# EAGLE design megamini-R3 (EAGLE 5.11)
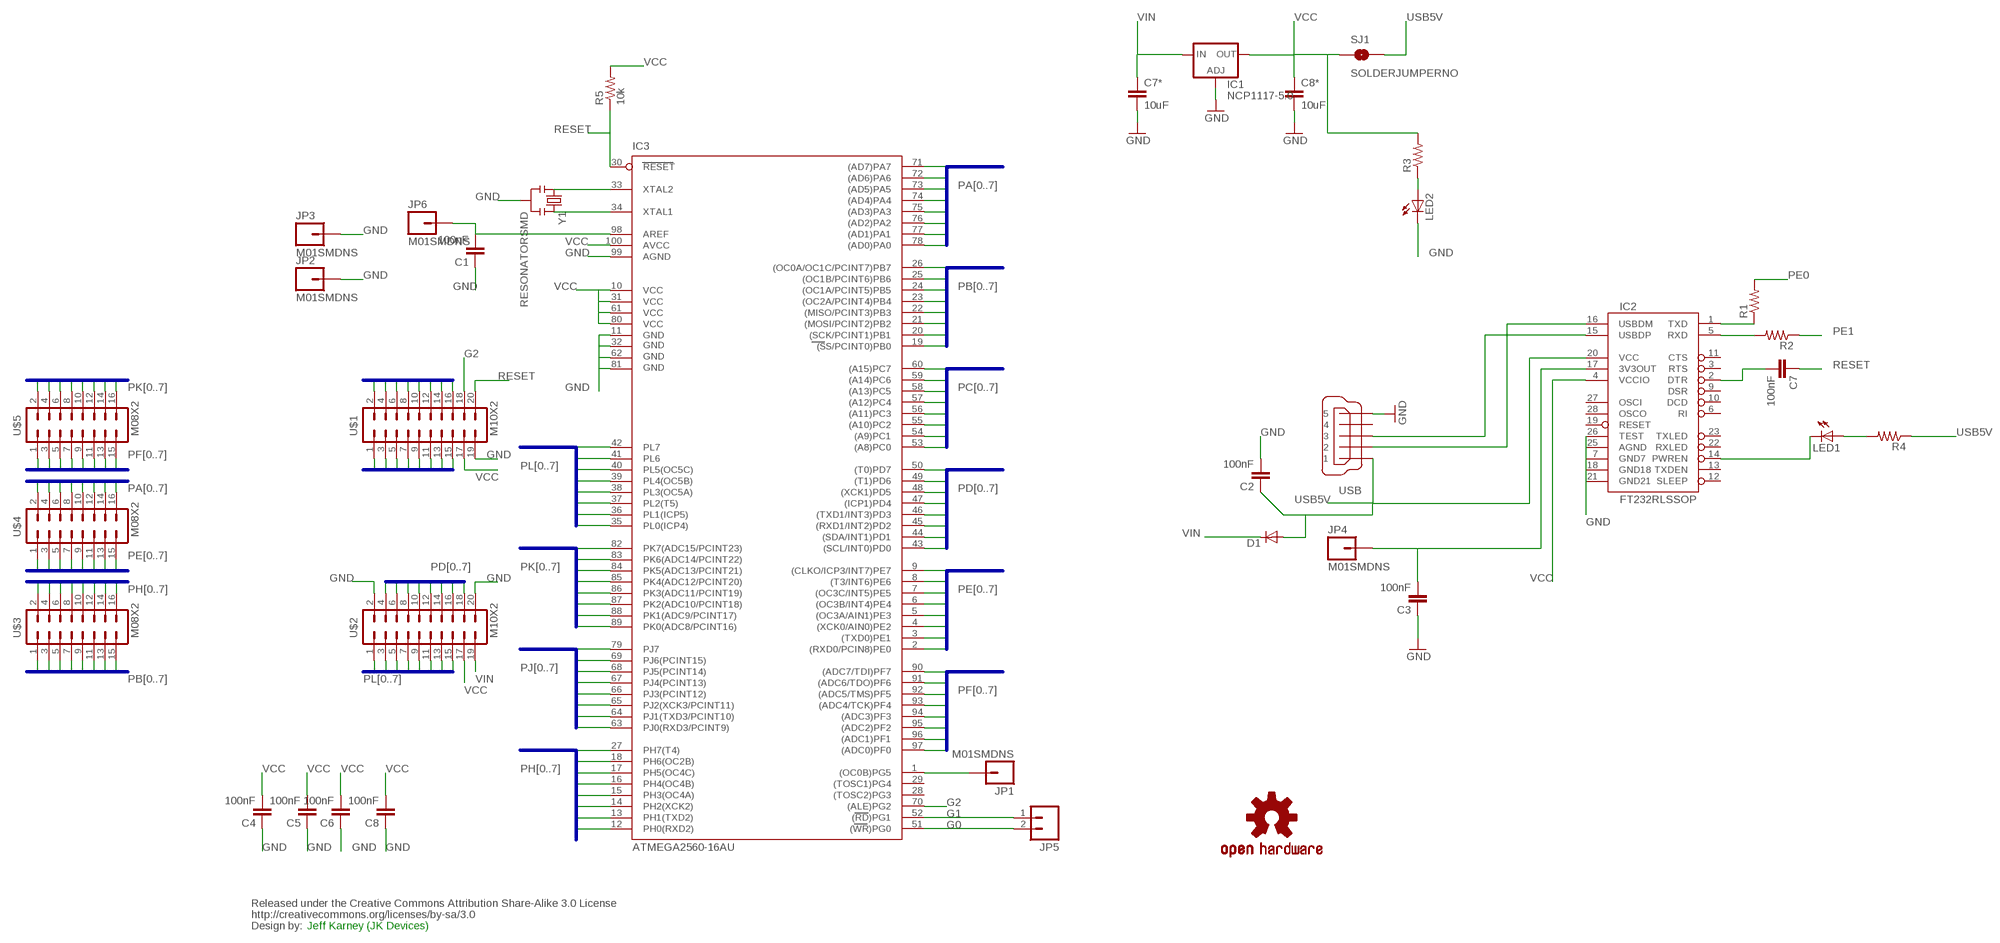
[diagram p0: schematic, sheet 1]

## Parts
C1  100nF  CAP0805  [0805]
C2  100nF  CAP0805  [0805]
C3  100nF  CAP0805  [0805]
C4  100nF  CAP0805  [0805]
C5  100nF  CAP0805  [0805]
C6  100nF  CAP0805  [0805]
C7  100nF  CAP0805  [0805]
C7*  10uF  CAP0805  [0805]
C8  100nF  CAP0805  [0805]
C8*  10uF  CAP0805  [0805]
D1  DIODESOD  [SOD-323]
IC1  NCP1117-5.0  LM317MDT  [DPACK]
IC2  FT232RLSSOP  [SSOP28DB]
IC3  ATMEGA2560-16AU  ATMEGA1280-16AU  [TQFP100]
JP1  M01SMDNS  [1X01NS]
JP2  M01SMDNS  [1X01NS]
JP3  M01SMDNS  [1X01NS]
JP4  M01SMDNS  [1X01NS]
JP5  M02PTH  [1X02]
JP6  M01SMDNS  [1X01NS]
LED1  LED0603  [LED-0603]
LED2  LED0603  [LED-0603]
R1  RESISTOR0805-RES  [0805]
R2  RESISTOR0805-RES  [0805]
R3  RESISTOR0805-RES  [0805]
R4  RESISTOR0805-RES  [0805]
R5  10k  RESISTOR0805-RES  [0805]
SJ1  SOLDERJUMPERNO  [SJ_2S-NO]
U$1  M10X2  [2X10]
U$2  M10X2  [2X10]
U$3  M08X2  [2X8_SMALL]
U$4  M08X2  [2X8_SMALL]
U$5  M08X2  [2X8_SMALL]
U$6  OSHW-LOGOS  [OSHW-LOGO-S]
U$7  CREATIVE_COMMONS  [CREATIVE_COMMONS]
USB  MINI-USB-UX60-MB-5ST  [UX60-MB-5ST]
Y1  RESONATORSMD  [RESONATOR-SMD]

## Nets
G0: IC3.51((WR)PG0) JP5.2
G1: IC3.52((RD)PG1) JP5.1
G2: IC3.70((ALE)PG2) U$1.18
GND: C1.1 C2.2 C3.1 C4.1 C5.1 C6.1 C7*.2 C8*.2 C8.1 IC1.1(ADJ) IC2.7(GND7) IC2.18(GND18) IC2.21(GND21) IC2.25(AGND) IC2.26(TEST) IC3.11(GND) IC3.32(GND1) IC3.62(GND2) IC3.81(GND3) IC3.99(AGND) JP2.1 JP3.1 LED2.C U$1.19 U$2.2 U$2.20 USB.5 Y1.2
N$1: IC2.16(USBDM) USB.2
N$2: IC3.1((OC0B)PG5) JP1.1
N$3: IC2.15(USBDP) USB.3
N$4: C7.2 IC2.2(DTR)
N$5: IC2.1(TXD) R1.1
N$6: IC2.5(RXD) R2.2
N$7: C3.2 IC2.17(3V3OUT) JP4.1
N$8: IC3.33(XTAL2) Y1.1
N$9: IC3.34(XTAL1) Y1.3
N$10: LED2.A R3.1
N$11: LED1.A R4.2
N$12: IC2.14(PWREN) LED1.C
N$13: C1.2 IC3.98(AREF) JP6.1
PA0: IC3.78((AD0)PA0) U$4.2
PA1: IC3.77((AD1)PA1) U$4.4
PA2: IC3.76((AD2)PA2) U$4.6
PA3: IC3.75((AD3)PA3) U$4.8
PA4: IC3.74((AD4)PA4) U$4.10
PA5: IC3.73((AD5)PA5) U$4.12
PA6: IC3.72((AD6)PA6) U$4.14
PA7: IC3.71((AD7)PA7) U$4.16
PB0: IC3.19((SS/PCINT0)PB0) U$3.15
PB1: IC3.20((SCK/PCINT1)PB1) U$3.13
PB2: IC3.21((MOSI/PCINT2)PB2) U$3.11
PB3: IC3.22((MISO/PCINT3)PB3) U$3.9
PB4: IC3.23((OC2A/PCINT4)PB4) U$3.7
PB5: IC3.24((OC1A/PCINT5)PB5) U$3.5
PB6: IC3.25((OC1B/PCINT6)PB6) U$3.3
PB7: IC3.26((OC0A/OC1C/PCINT7)PB7) U$3.1
PC0: IC3.53((A8)PC0) U$1.15
PC1: IC3.54((A9)PC1) U$1.13
PC2: IC3.55((A10)PC2) U$1.11
PC3: IC3.56((A11)PC3) U$1.9
PC4: IC3.57((A12)PC4) U$1.7
PC5: IC3.58((A13)PC5) U$1.5
PC6: IC3.59((A14)PC6) U$1.3
PC7: IC3.60((A15)PC7) U$1.1
PD0: IC3.43((SCL/INT0)PD0) U$2.4
PD1: IC3.44((SDA/INT1)PD1) U$2.6
PD2: IC3.45((RXD1/INT2)PD2) U$2.8
PD3: IC3.46((TXD1/INT3)PD3) U$2.10
PD4: IC3.47((ICP1)PD4) U$2.12
PD5: IC3.48((XCK1)PD5) U$2.14
PD6: IC3.49((T1)PD6) U$2.16
PD7: IC3.50((T0)PD7) U$2.18
PE0: IC3.2((RXD0/PCIN8)PE0) R1.2 U$4.15
PE1: IC3.3((TXD0)PE1) R2.1 U$4.13
PE2: IC3.4((XCK0/AIN0)PE2) U$4.11
PE3: IC3.5((OC3A/AIN1)PE3) U$4.9
PE4: IC3.6((OC3B/INT4)PE4) U$4.7
PE5: IC3.7((OC3C/INT5)PE5) U$4.5
PE6: IC3.8((T3/INT6)PE6) U$4.3
PE7: IC3.9((CLKO/ICP3/INT7)PE7) U$4.1
PF0: IC3.97((ADC0)PF0) U$5.15
PF1: IC3.96((ADC1)PF1) U$5.13
PF2: IC3.95((ADC2)PF2) U$5.11
PF3: IC3.94((ADC3)PF3) U$5.9
PF4: IC3.93((ADC4/TCK)PF4) U$5.7
PF5: IC3.92((ADC5/TMS)PF5) U$5.5
PF6: IC3.91((ADC6/TDO)PF6) U$5.3
PF7: IC3.90((ADC7/TDI)PF7) U$5.1
PH0: IC3.12(PH0(RXD2)) U$3.16
PH1: IC3.13(PH1(TXD2)) U$3.14
PH2: IC3.14(PH2(XCK2)) U$3.12
PH3: IC3.15(PH3(OC4A)) U$3.10
PH4: IC3.16(PH4(OC4B)) U$3.8
PH5: IC3.17(PH5(OC4C)) U$3.6
PH6: IC3.18(PH6(OC2B)) U$3.4
PH7: IC3.27(PH7(T4)) U$3.2
PJ0: IC3.63(PJ0(RXD3/PCINT9)) U$1.2
PJ1: IC3.64(PJ1(TXD3/PCINT10)) U$1.4
PJ2: IC3.65(PJ2(XCK3/PCINT11)) U$1.6
PJ3: IC3.66(PJ3(PCINT12)) U$1.8
PJ4: IC3.67(PJ4(PCINT13)) U$1.10
PJ5: IC3.68(PJ5(PCINT14)) U$1.12
PJ6: IC3.69(PJ6(PCINT15)) U$1.14
PJ7: IC3.79(PJ7) U$1.16
PK0: IC3.89(PK0(ADC8/PCINT16)) U$5.16
PK1: IC3.88(PK1(ADC9/PCINT17)) U$5.14
PK2: IC3.87(PK2(ADC10/PCINT18)) U$5.12
PK3: IC3.86(PK3(ADC11/PCINT19)) U$5.10
PK4: IC3.85(PK4(ADC12/PCINT20)) U$5.8
PK5: IC3.84(PK5(ADC13/PCINT21)) U$5.6
PK6: IC3.83(PK6(ADC14/PCINT22)) U$5.4
PK7: IC3.82(PK7(ADC15/PCINT23)) U$5.2
PL0: IC3.35(PL0(ICP4)) U$2.1
PL1: IC3.36(PL1(ICP5)) U$2.3
PL2: IC3.37(PL2(T5)) U$2.5
PL3: IC3.38(PL3(OC5A)) U$2.7
PL4: IC3.39(PL4(OC5B)) U$2.9
PL5: IC3.40(PL5(OC5C)) U$2.11
PL6: IC3.41(PL6) U$2.13
PL7: IC3.42(PL7) U$2.15
RESET: C7.1 IC3.30(RESET) R5.1 U$1.20
USB5V: C2.1 D1.2(A) IC2.20(VCC) R4.1 SJ1.2 USB.1
VCC: C4.2 C5.2 C6.2 C8*.1 C8.2 IC1.4(OUT) IC2.4(VCCIO) IC3.10(VCC) IC3.31(VCC1) IC3.61(VCC2) IC3.80(VCC3) IC3.100(AVCC) R3.2 R5.2 SJ1.1 U$1.17 U$2.17
VIN: C7*.1 D1.1(C) IC1.3(IN) U$2.19
Unconnected: IC2.3(RTS) IC2.6(RI) IC2.9(DSR) IC2.10(DCD) IC2.11(CTS) IC2.12(SLEEP) IC2.13(TXDEN) IC2.19(RESET) IC2.22(RXLED) IC2.23(TXLED) IC2.27(OSCI) IC2.28(OSCO) IC3.28((TOSC2)PG3) IC3.29((TOSC1)PG4) USB.4

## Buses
PB[0..7]
PH[0..7]
PE[0..7]
PA[0..7]
PF[0..7]
PK[0..7]
PL[0..7]
PD[0..7]
PC[0..7]
PJ[0..7]

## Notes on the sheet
- Jeff Karney (JK Devices)

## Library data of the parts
C1-C7 C7* C8 C8* = SparkFun:CAP: Capacitor
D1 = SparkFun:DIODE: Diode
IC1 = v-reg:LM317?*: 500 mA Adjustable Output Positive Voltage Regulator Source: http://www.onsemi.co.jp .. LM317M-D.PDF
IC2 = SparkFun:FT232RL: USB UART FT232RL 4th Generation USB UART (USB <-> Serial) Controller. Spark Fun Electronics SKU : COM-00650
IC3 = atmel-2005:ATMEGA*: MICROCONTROLLER 64/128/256 Kbytes FLASH 4 Kbytes EEPROM 8 Kbytes SRAM 86 General Purpose I/O pins 12-channels16-bit PWM 4 x Serial USARTs 16-channels 10-bit A/D
JP1-JP4 JP6 = SparkFun:M01: Header 1
JP5 = SparkFun:M02: Header 2
LED1 LED2 = SparkFun:LED: LEDs
R1-R5 = SparkFun:RESISTOR: Resistor
SJ1 = SparkFun:SOLDERJUMPER: Solder Jumper
U$1 U$2 = SparkFun:M10X2: This was SPECIALLY designed to be used with our Graphic LCD Backpack. Be sure you want to use this! It is not only staggered on each line of header holes, but IT IS ALSO offset of the center point of the top and bottom lines by 5 mil. This causes the headers to lock into place on the "standard"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
U$3-U$5 = SparkFun:M08X2
U$6 = SparkFun:OSHW-LOGO: Open Source Hardware Logo This logo indicates the piece of hardware it is found on incorporates a OSHW license and/or adheres to the definition of open source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
U$7 = SparkFun:CREATIVE_COMMONS
USB = con-hirose:MINI-USB-: MINI USB Connector Source: http://www.hirose.co.jp/cataloge_hp/e24000019.pdf; OC_FARNELL: unknown; OC_NEWARK: unknown
Y1 = SparkFun:RESONATOR: Resonator Small SMD resonator. This is the itty bitty 10/20MHz resonators with built in caps. CSTCE10M0G55 and CSTCE20M0V53. Footprint has been reviewed closely but hasn't been tested yet.

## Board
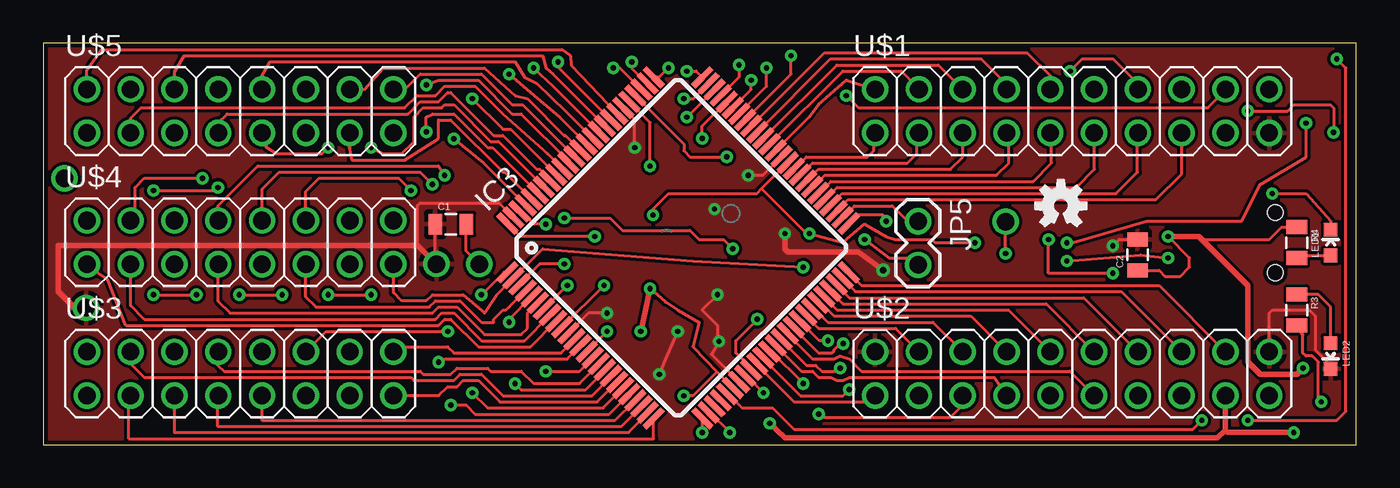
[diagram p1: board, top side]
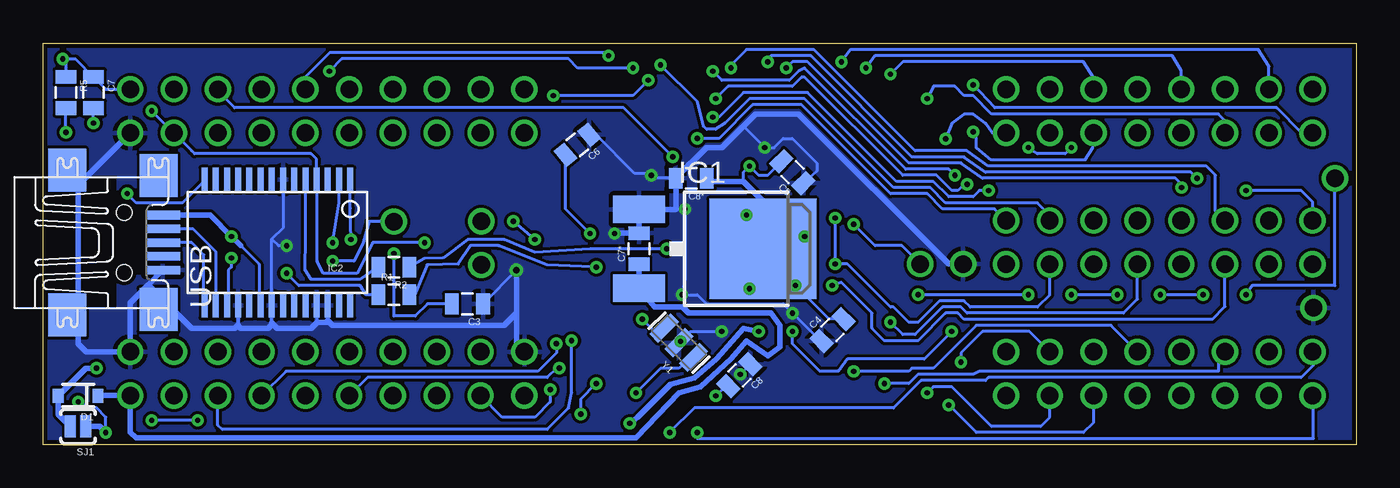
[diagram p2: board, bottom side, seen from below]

Size 76.17 x 23.32 mm. Coordinates in mm from the lower left corner, seen from the top.
Outline: 0,0 76.17,0 76.17,23.32 0,23.32 0,0
Copper layers (1*16): Top 0.0356mm / dielectric 1.5011mm / Bottom 0.0356mm
Design rules "SilverCircuits *": minimum track width 7mil, minimum drill 12mil, track to track 7mil, track to pad 7mil, pad to pad 7mil, via to via 7mil, smd to smd 0mil, copper to edge 10mil, drill to drill 8mil, minimum pad ring 10mil, minimum via ring 8mil, stop-mask expansion 4mil, vias tented up to drill 14mil, thermal gap 10mil

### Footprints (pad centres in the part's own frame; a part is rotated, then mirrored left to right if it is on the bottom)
0805 = smd 0.8 x 1.2: 1 -0.9,0; 2 0.9,0
SOD-323 = smd 0.63 x 0.83: 1 -1.15,0; 2 1.15,0
DPACK = smd 1.6 x 3: 1 -2.28,-4.8; 3 2.28,-4.8 | smd 5.8 x 6.2: 4 0,2.38
SSOP28DB = smd 0.348 x 1.397: 1 -4.225,-3.656; 2 -3.575,-3.656; 3 -2.925,-3.656; 4 -2.275,-3.656; 5 -1.625,-3.656; 6 -0.975,-3.656; 7 -0.325,-3.656; 8 0.325,-3.656; 9 0.975,-3.656; 10 1.625,-3.656; 11 2.275,-3.656; 12 2.925,-3.656; 13 3.575,-3.656; 14 4.225,-3.656; 15 4.225,3.656; 16 3.575,3.656; 17 2.925,3.656; 18 2.275,3.656; 19 1.625,3.656; 20 0.975,3.656; 21 0.325,3.656; 22 -0.325,3.656; 23 -0.975,3.656; 24 -1.625,3.656; 25 -2.275,3.656; 26 -2.925,3.656; 27 -3.575,3.656; 28 -4.225,3.656
TQFP100 = smd 1.5 x 0.35: 1 -8,6; 2 -8,5.5; 3 -8,5; 4 -8,4.5; 5 -8,4; 6 -8,3.5; 7 -8,3; 8 -8,2.5; 9 -8,2; 10 -8,1.5; 11 -8,1; 12 -8,0.5; 13 -8,0; 14 -8,-0.5; 15 -8,-1; 16 -8,-1.5; 17 -8,-2; 18 -8,-2.5; 19 -8,-3; 20 -8,-3.5; 21 -8,-4; 22 -8,-4.5; 23 -8,-5; 24 -8,-5.5; 25 -8,-6; 51 8,-6; 52 8,-5.5; 53 8,-5; 54 8,-4.5; 55 8,-4; 56 8,-3.5; 57 8,-3; 58 8,-2.5; 59 8,-2; 60 8,-1.5; 61 8,-1; 62 8,-0.5; 63 8,0; 64 8,0.5; 65 8,1; 66 8,1.5; 67 8,2; 68 8,2.5; 69 8,3; 70 8,3.5; 71 8,4; 72 8,4.5; 73 8,5; 74 8,5.5; 75 8,6 | smd 0.35 x 1.5: 26 -6,-8; 27 -5.5,-8; 28 -5,-8; 29 -4.5,-8; 30 -4,-8; 31 -3.5,-8; 32 -3,-8; 33 -2.5,-8; 34 -2,-8; 35 -1.5,-8; 36 -1,-8; 37 -0.5,-8; 38 0,-8; 39 0.5,-8; 40 1,-8; 41 1.5,-8; 42 2,-8; 43 2.5,-8; 44 3,-8; 45 3.5,-8; 46 4,-8; 47 4.5,-8; 48 5,-8; 49 5.5,-8; 50 6,-8; 76 6,8; 77 5.5,8; 78 5,8; 79 4.5,8; 80 4,8; 81 3.5,8; 82 3,8; 83 2.5,8; 84 2,8; 85 1.5,8; 86 1,8; 87 0.5,8; 88 0,8; 89 -0.5,8; 90 -1,8; 91 -1.5,8; 92 -2,8; 93 -2.5,8; 94 -3,8; 95 -3.5,8; 96 -4,8; 97 -4.5,8; 98 -5,8; 99 -5.5,8; 100 -6,8
1X01NS = drill 1.016 pad 1.524 round: 1 0,0
1X02 = drill 1.016 pad 1.524 round: 1 0,0; 2 2.54,0
LED-0603 = smd 0.8 x 0.8: A 0,-0.75; C 0,0.75
SJ_2S-NO = smd 0.635 x 1.27: 1 -0.45,0; 2 0.45,0
2X10 = drill 1.016 pad 1.524 round: 1 -11.43,-1.27; 2 -11.43,1.27; 3 -8.89,-1.27; 4 -8.89,1.27; 5 -6.35,-1.27; 6 -6.35,1.27; 7 -3.81,-1.27; 8 -3.81,1.27; 9 -1.27,-1.27; 10 -1.27,1.27; 11 1.27,-1.27; 12 1.27,1.27; 13 3.81,-1.27; 14 3.81,1.27; 15 6.35,-1.27; 16 6.35,1.27; 17 8.89,-1.27; 18 8.89,1.27; 19 11.43,-1.27; 20 11.43,1.27
2X8_SMALL = drill 1.016 pad 1.524 round: 1 0,0; 2 0,2.54; 3 2.54,0; 4 2.54,2.54; 5 5.08,0; 6 5.08,2.54; 7 7.62,0; 8 7.62,2.54; 9 10.16,0; 10 10.16,2.54; 11 12.7,0; 12 12.7,2.54; 13 15.24,0; 14 15.24,2.54; 15 17.78,0; 16 17.78,2.54
UX60-MB-5ST = smd 2 x 0.5: 1 2.25,1.6; 2 2.25,0.8; 3 2.25,0; 4 2.25,-0.8; 5 2.25,-1.6 | smd 2.2 x 2.5: M1 -3.3,-4.2; M2 -3.3,4.2; M3 2,3.882; M4 2,-3.882 | hole 0.9: 0,-1.75; 0,1.75
RESONATOR-SMD = smd 0.7 x 1.7: 1 -1.2,0; 2 0,0; 3 1.2,0

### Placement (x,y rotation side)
C1  23.65,12.8 0 top
C2  63.47,11.02 90 top
C3  51.56,8.18 180 bottom
C4  30.38,6.66 45 bottom
C5  32.72,15.82 135 bottom
C6  45.19,17.41 220 bottom
C7  73.25,20.45 270 bottom
C7*  41.61,11.38 90 bottom
C8  35.79,4.04 225 bottom
C8*  38.58,15.47 180 bottom
D1  74.14,2.84 180 bottom
IC1  36.8,11.38 270 bottom
IC2  62.59,11.73 180 bottom
IC3  36.83,11.43 45 top
JP1  1.24,15.47 0 top
JP2  2.49,7.95 0 top
JP3  22.81,10.49 0 top
JP4  55.83,12.95 0 top
JP5  50.75,12.98 270 top
JP6  25.3,10.49 0 top
LED1  74.68,11.73 0 top
LED2  74.68,5.16 180 top
R1  55.83,8.71 0 bottom
R2  55.83,10.31 180 bottom
R3  72.72,7.82 270 top
R4  72.72,11.73 270 top
R5  74.85,20.45 270 bottom
SJ1  74.14,1.07 180 bottom
U$1  59.69,19.37 0 top
U$2  59.69,4.13 0 top
U$3  2.54,2.86 0 top
U$4  2.54,10.48 0 top
U$5  2.54,18.1 0 top
U$6  59.03,13.87 0 top
U$7  not placed on the board
USB  71.48,11.73 0 bottom
Y1  39.29,5.93 135 bottom

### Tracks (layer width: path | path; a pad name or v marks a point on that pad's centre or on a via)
G0  (via drill 0.3)
  Top 0.178: IC3.51 47.22,13.34 48.72,13.34 48.9,13.16 v48.9,12.98 | v47.65,11.91 49.07,10.85 50.32,10.85 50.72,10.44 JP5.2
  Bottom 0.178: v47.65,11.91 v48.9,12.98
G1
  Top 0.178: IC3.52 47.05,13.87 49.25,13.87 50.14,12.98 JP5.1
G2  (via drill 0.3)
  Top 0.178: IC3.70 41.07,20.62 v41.07,21.16 | v46.58,20.27 47.3,19.56 67.56,19.56 68.58,20.57 U$1.18
  Bottom 0.178: v41.07,21.16 41.96,20.27 v46.58,20.27
GND  (via drill 0.3, 0.38)
  Top 0.178: IC3.99 26.44,14.05 21.87,14.05 21.72,13.89 21.72,11.58 | IC3.32 38.76,5.26 v39.2,6.01 | 39.12,6.04 39.12,6.93 38.23,7.82 v39.12,8.71 | 39.12,6.04 v39.2,6.01 | IC3.62 41.75,15.65 v40.89,15.65 | IC3.81 34.31,18.89 v34.31,17.25 | v39.2,6.01 39.12,5.93 39.12,6.04 | IC3.11 31.63,7.64 v32.72,7.64 | LED2.C 74.68,4.62 73.79,5.51 73.79,7.47 73.43,7.82 71.3,7.82 71.12,7.64 U$2.20 | C1.1 22.75,10.55 JP3.1 | C2.2 62.42,11.92 v62.05,11.56 | v35.74,4.09 36.09,4.98 v36.8,6.58
  Top 0.305: 1.83,7.95 0.89,8.89 0.89,11.58 21.72,11.58 JP3.1 | v48.72,10.13 47.3,11.2 43.2,11.2 43.03,11.38 v43.03,12.27
  Top 0.356: JP2.1 1.83,7.95
  Bottom 0.178: 39.47,13.69 v38.94,13.69 38.94,9.6 v39.12,8.71 38.23,8.71 37.69,8.18 33.25,8.18 v32.72,7.64 31.09,6.03 C4.1 | C8*.2 40.72,15.47 v40.89,15.65 41,15.75 41.86,15.75 44.1,17.99 C6.1 | 35.65,18.4 35.47,18.4 v34.31,17.25 33.78,17.25 33.25,17.78 32.72,17.78 31.29,16.36 31.29,15.9 C5.1 | Y1.2 39.2,5.83 v39.2,6.01 38.63,6.58 v36.8,6.58 | 64.86,6.9 IC2.18 64.86,6.97 | 62.94,6.93 62.94,8.05 IC2.21 | 62.91,7.08 IC2.21 | 60.27,7.11 60.27,8.04 IC2.25 | 59.74,7.11 59.66,7.19 IC2.26 59.66,7.21 | IC2.7 62.23,15.36 62.23,12.62 62.91,11.94 | IC2.21 62.91,11.94 | v48.72,10.13 C3.1 | v62.05,11.56 62.52,11.56 62.91,11.94 | C8.1 | v35.74,4.09 C8.1
  Bottom 0.305: JP3.1 23.65,10.49 32.36,19.2 34.85,19.2 35.65,18.4 36.8,17.25 37.7,17.25 C8*.2 39.47,15.46 39.47,13.69 39.5,13.66 IC1.1 C7*.2 43.02,12.28 v43.03,12.27 | 70.08,9.28 71.12,8.24 U$2.20 73.67,5.4 74.14,5.87 74.14,15.07 U$1.19 | 70.08,9.28 USB.5 | 64.86,6.9 64.72,6.76 63.12,6.76 62.94,6.93 | 62.91,7.08 62.59,6.76 60.63,6.76 60.27,7.11 59.74,7.11 | 64.86,6.97 65.08,6.76 67.56,6.76 70.08,9.28 | U$2.2 48.72,5.86 48.72,7.64 | v48.72,10.13 48.72,7.64 | 59.66,7.21 59.38,6.93 49.43,6.93 48.72,7.64
  pour Top: -2.31,25.43 -2.31,-2.67 79.3,-2.67 78.94,26.49 -0.36,25.96
  pour Bottom: -0.53,24.18 80.72,24.18 80.72,-1.07 -3.2,-1.07 -3.2,24
N$1
  Bottom 0.178: USB.2 67.47,12.54 66.14,11.2 66.14,8.1 IC2.16
N$2  (via drill 0.3)
  Top 0.178: IC3.1 26.73,10.02 v25.43,8.71 | v16.54,8.71 v19.02,8.71 | v11.38,8.71 v13.87,8.71 | v6.4,8.71 v8.89,8.71
  Bottom 0.178: v19.02,8.71 v25.43,8.71 | v13.87,8.71 v16.54,8.71 | v8.89,8.71 v11.38,8.71 | JP1.1 1.25,9.25 6.04,9.25 v6.4,8.71
N$3
  Bottom 0.178: USB.3 67.56,11.73 66.85,11.02 66.85,8.12 IC2.15
N$4  (via drill 0.3)
  Top 0.178: v59.38,11.73 59.74,11.73 64.01,12.98 69.52,12.98 70.59,15.11 73.25,16.71 v73.25,18.67
  Bottom 0.178: IC2.2 59.01,14.06 v59.38,11.73 | v73.25,18.67 C7.2
N$5  (via drill 0.3)
  Top 0.178: v62.05,9.96 58.32,9.96 v58.32,11.91
  Bottom 0.178: R1.1 57.44,8.71 57.78,9.25 61.34,9.25 v62.05,9.96 | v58.32,11.91 58.36,13.73 IC2.1
N$6
  Bottom 0.178: R2.2 57.78,9.6 60.63,9.6 60.98,10.13 60.96,12.07 IC2.5
N$7  (via drill 0.3)
  Top 0.178: v65.25,10.85 63.65,11.02 v59.38,10.67 | v55.83,11.1 JP4.1
  Bottom 0.178: IC2.17 65.43,8.16 65.43,10.13 65.25,10.31 v65.25,10.85 | v59.38,10.67 58.14,10.67 57.61,11.73 57.28,12.95 JP4.1 | v55.83,11.1 55.83,7.47 54.59,7.47 53.87,8.18 C3.2
N$8  (via drill 0.3)
  Top 0.178: IC3.33 40.8,4 v41.78,3.02
  Bottom 0.178: v41.78,3.02 40.36,4.45 39.29,4.45 38.66,5.08 Y1.1
N$9  (via drill 0.3)
  Top 0.178: IC3.34 41.07,4.44 40.18,5.33 40.18,6.04 v41.43,7.29
  Bottom 0.178: v41.43,7.29 40.52,6.4 Y1.3
N$10
  Top 0.178: R3.1 73.95,8.72 74.68,8 LED2.A
N$11
  Top 0.178: LED1.A 72.87,10.98 R4.2
N$12  (via drill 0.3)
  Top 0.178: LED1.C 74.68,12.98 73.25,14.58 v71.3,14.58
  Bottom 0.178: IC2.14 66.81,15.33 68.1,14.05 70.76,14.05 v71.3,14.58
N$13  (via drill 0.3)
  Top 0.178: C1.2 24.55,11.24 JP6.1 | IC3.98 27.7,13.55 28.45,12.8 v29.16,12.8
  Bottom 0.178: v29.16,12.8 27.91,11.56 26.36,11.56 JP6.1
PA0  (via drill 0.3)
  Top 0.178: v6.4,14.76 9.96,14.76 v10.13,14.94 | v33.07,21.87 33.46,21.87 IC3.78
  Bottom 0.178: U$4.2 2.54,14.1 3.2,14.76 v6.4,14.76 | v10.13,14.94 10.13,15.11 10.49,15.47 21.69,15.47 22.94,16.36 25.96,16.36 31.83,22.23 32.72,22.23 v33.07,21.87
PA1  (via drill 0.3)
  Top 0.178: IC3.77 35.03,20.98 34.14,21.87 v34.14,22.23 | v9.25,15.47 5.87,15.47 5.33,14.94 5.33,13.27 U$4.4
  Bottom 0.178: v34.14,22.23 34.14,22.4 33.96,22.58 31.65,22.58 25.78,16.71 22.76,16.71 21.51,15.82 9.6,15.82 v9.25,15.47
PA2  (via drill 0.3)
  Top 0.178: IC3.76 35.73,21.33 v36.27,21.87
  Bottom 0.178: v36.27,21.87 36.27,22.05 35.38,22.94 31.47,22.94 25.6,17.07 22.58,17.07 21.34,16.18 8.71,16.18 8.18,15.65 8.18,13.58 U$4.6
PA3  (via drill 0.3)
  Top 0.178: U$4.8 10.16,13.89 12.45,16.18 22.94,16.18 v23.29,15.65 | v37.34,21.69 37.88,21.69 IC3.75
  Bottom 0.178: v23.29,15.65 23.65,16 26.14,16 32,21.87 32.36,21.69 32.89,21.16 36.8,21.16 v37.34,21.69
PA4  (via drill 0.3)
  Top 0.178: U$4.10 12.7,14.83 13.69,15.82 21.87,15.82 v22.58,15.11 | v37.16,20.09 37.71,20.09 IC3.74
  Bottom 0.178: v22.58,15.11 22.76,15.11 23.11,14.76 23.47,14.76 24.36,15.65 26.31,15.65 32,21.34 32.18,21.34 32.72,20.8 36.45,20.8 v37.16,20.09
PA5  (via drill 0.3)
  Top 0.178: U$4.12 15.24,14.71 16,15.47 20.62,15.47 v21.34,14.76 | v37.34,19.02 38.94,20.62 IC3.73
  Bottom 0.178: v21.34,14.76 21.87,14.76 22.23,14.4 23.65,14.4 24.54,15.29 26.67,15.29 31.83,20.45 35.56,20.45 36.98,19.02 v37.34,19.02
PA6  (via drill 0.3)
  Top 0.178: IC3.72 40.36,21.32 v40.36,22.05
  Bottom 0.178: v40.36,22.05 38.23,19.91 37.87,18.49 37.69,18.31 37.16,18.31 36.63,18.67 35.2,20.09 32,20.09 26.85,14.94 24.71,14.94 23.82,14.05 18.49,14.05 17.78,13.34 U$4.14
PA7  (via drill 0.3)
  Top 0.178: v38.23,17.78 38.23,18.48 IC3.71
  Bottom 0.178: U$4.16 20.99,13.69 24,13.69 24.89,14.58 27.03,14.58 32.18,19.74 35.03,19.74 36.98,17.78 v38.23,17.78
PB0
  Top 0.178: U$3.15 22.95,2.86 23.47,3.38 24,3.38 24.36,3.73 25.25,3.73 26.49,2.49 32.13,2.49 IC3.19
PB1  (via drill 0.3)
  Top 0.178: v24.89,3.02 25.78,2.13 32.48,2.13 IC3.20
  Bottom 0.178: U$3.13 17.78,1.6 18.31,1.07 21.16,1.07 23.47,3.38 24.54,3.38 v24.89,3.02
PB2  (via drill 0.3)
  Top 0.178: v23.65,2.31 24.54,2.31 25.07,1.78 32.84,1.78 IC3.21
  Bottom 0.178: U$3.11 15.24,1.29 15.82,0.71 22.05,0.71 v23.65,2.31
PB3
  Top 0.178: U$3.9 12.7,1.42 33.19,1.42 IC3.22
PB4
  Top 0.178: U$3.7 10.13,2.86 10.13,1.07 33.54,1.07 IC3.23
PB5
  Top 0.178: IC3.24 35.06,1.81 33.96,0.71 7.62,0.71 U$3.5
PB6
  Top 0.178: IC3.25 35.42,0.36 4.98,0.36 4.98,2.86 U$3.3
PB7  (via drill 0.3)
  Top 0.178: IC3.26 38.24,0.71 v38.23,0.71
  Bottom 0.178: v38.23,0.71 38.23,0.36 2.49,0.36 2.49,2.86 U$3.1
PC0
  Top 0.178: IC3.53 46.7,14.22 64.54,14.22 66.04,15.72 U$1.15
PC1
  Top 0.178: IC3.54 46.34,14.58 62.23,14.58 63.48,15.82 63.48,18.07 U$1.13
PC2
  Top 0.178: IC3.55 45.37,14.26 46.05,14.94 59.92,14.94 60.98,16 60.98,18.07 U$1.11
PC3
  Top 0.178: IC3.56 45.02,14.61 45.7,15.29 57.43,15.29 58.5,16.36 58.5,18.02 U$1.9
PC4
  Top 0.178: IC3.57 44.66,14.97 45.34,15.65 55.3,15.65 56.01,16.36 56.01,17.97 U$1.7
PC5
  Top 0.178: IC3.58 44.3,15.32 44.98,16 52.63,16 53.34,16.71 U$1.5
PC6
  Top 0.178: IC3.59 43.94,15.67 44.63,16.36 50.14,16.36 50.67,16.89 50.67,17.97 U$1.3
PC7
  Top 0.178: IC3.60 43.59,16.03 44.27,16.71 47.83,16.71 48.18,17.07 48.18,18.02 U$1.1
PD0
  Top 0.178: IC3.43 44.26,7.49 44.98,6.76 49.44,6.76 U$2.4
PD1
  Top 0.178: IC3.44 44.73,7.89 45.52,7.11 51.63,7.11 U$2.6
PD2
  Top 0.178: IC3.45 45.09,8.25 45.87,7.47 53.81,7.47 U$2.8
PD3
  Top 0.178: IC3.46 45.31,8.56 46.05,7.82 55.99,7.82 U$2.10
PD4
  Top 0.178: IC3.47 45.67,8.92 46.41,8.18 58.18,8.18 U$2.12
PD5
  Top 0.178: IC3.48 46.02,9.27 46.76,8.53 60.36,8.53 U$2.14
PD6
  Top 0.178: IC3.49 46.38,9.63 47.12,8.89 62.55,8.89 U$2.16
PD7
  Top 0.178: IC3.50 46.73,9.99 47.47,9.25 64.73,9.25 U$2.18
PE0  (via drill 0.3)
  Top 0.178: U$4.15 20.32,8.84 20.8,8.36 22.23,8.36 22.58,8.71 24.36,8.71 25.6,7.64 26.31,8.71 27.26,9.66 IC3.2 27.28,9.68 28.98,11.38 37.69,10.67 v44.09,10.31
  Bottom 0.178: v44.09,10.31 44.27,10.31 46.94,10.44 49.78,11.56 51.38,11.56 52.09,10.49 53.91,10.44 54.62,8.71 R1.2
PE1  (via drill 0.3)
  Top 0.178: IC3.3 27.64,9.32 28.8,10.49 v30.23,10.49 | v40.01,11.38 39.47,11.91 38.05,11.91 37.52,12.45 33.6,12.45 32.89,13.16 v30.23,13.16
  Bottom 0.178: U$4.13 17.78,8.71 18.49,8 22.4,8 22.76,8.36 24.18,8.36 25.43,7.11 25.96,7.11 26.85,8 27.03,8 29.52,10.49 v30.23,10.49 v30.23,13.16 | v40.01,11.38 44.45,11.38 47.65,11.18 49.43,11.91 51.56,11.91 52.98,10.85 54.05,10.82 R2.1
PE2
  Top 0.178: U$4.11 15.24,8.59 15.82,8 22.4,8 22.76,8.36 24.18,8.36 25.43,7.11 26.14,7.11 26.14,7.29 26.67,7.82 26.85,7.82 27.03,8 27.04,8 IC3.4
PE3  (via drill 0.3)
  Top 0.178: IC3.5 27.03,7.28 v27.03,7.11
  Bottom 0.178: v27.03,7.11 26.31,6.4 25.6,6.4 24,8 22.94,8 22.58,7.64 13.51,7.64 12.7,8.46 U$4.9
PE4
  Top 0.178: IC3.6 28.09,7.64 28.09,6.76 27.74,6.4 25.6,6.4 24,8 22.94,8 22.58,7.64 10.85,7.64 10.16,8.33 U$4.7
PE5  (via drill 0.3)
  Top 0.178: IC3.7 v30.4,9.25
  Bottom 0.178: v30.4,9.25 29.87,9.42 28.09,7.64 28.09,6.76 27.38,6.04 25.43,6.04 23.82,7.64 23.11,7.64 22.76,7.29 8.36,7.29 7.62,8.03 U$4.5
PE6
  Top 0.178: IC3.8 29.34,7.47 27.91,6.04 25.43,6.04 23.82,7.64 23.11,7.64 22.76,7.29 5.87,7.29 5.08,8.08 U$4.3
PE7
  Top 0.178: IC3.9 29.76,7.18 28.27,5.69 25.25,5.69 23.65,7.29 23.29,7.29 22.94,6.93 4.8,6.93 3.73,9.6 2.49,10.43 U$4.1
PF0  (via drill 0.3)
  Top 0.178: v23.82,17.75 25.54,16.36 IC3.97
  Bottom 0.178: U$5.15 21.12,18.1 21.51,18.67 22.23,19.2 22.76,19.2 23.47,18.67 v23.82,17.75
PF1
  Top 0.178: U$5.13 17.78,17.25 17.92,16.54 20.98,16.54 22.94,17.78 22.94,18.85 23.65,18.85 26.67,15.82 26.78,15.82 IC3.96
PF2  (via drill 0.3)
  Top 0.178: v22.23,18.16 22.23,19.02 22.58,19.2 23.82,19.2 25.78,17.25 26.06,17.25 IC3.95
  Bottom 0.178: U$5.11 15.29,17.25 15.73,16.54 21.16,16.54 22.05,17.25 22.05,17.78 v22.23,18.16
PF3  (via drill 0.3)
  Top 0.178: U$5.9 12.98,17.25 13.51,16.89 16.18,16.89 v16.54,17.25 | 28.95,14.97 IC3.94 26.41,17.6 25.96,17.6 23.82,19.74 23.29,19.74 23.11,19.56 22.05,19.56 21.51,19.02 21.51,17.6 20.8,16.89 19.74,16.89 v19.02,17.25
  Bottom 0.178: v16.54,17.25 16.89,16.89 18.49,16.89 v19.02,17.25
PF4
  Top 0.178: U$5.7 10.16,18.69 10.67,19.2 21.16,19.2 21.87,19.91 22.94,19.91 23.47,20.45 23.65,20.45 26.14,17.96 26.67,17.96 28.63,16 28.8,16 29.34,15.47 IC3.93
PF5  (via drill 0.3)
  Top 0.178: v24.89,20.09 26.67,18.31 27.12,18.31 IC3.92
  Bottom 0.178: U$5.5 7.62,18.82 8,19.2 21.16,19.2 22.23,20.27 22.76,20.27 23.29,20.8 24.54,20.8 v24.89,20.09
PF6
  Top 0.178: U$5.3 5.08,18.95 5.69,19.56 20.98,19.56 21.69,20.27 22.76,20.27 23.29,20.8 25.07,20.8 26.67,19.2 29.25,16.89 IC3.91
PF7  (via drill 0.3)
  Top 0.178: v22.23,20.89 22.94,21.16 25.25,21.16 27.2,19.2 27.74,19.2 30.47,16.47 IC3.90
  Bottom 0.178: U$5.1 3.16,18.1 4.62,19.56 20.98,19.56 v22.23,20.89
PH0
  Top 0.178: IC3.12 30.82,6.11 30.05,5.33 23.82,5.33 23.47,5.69 20.61,5.69 U$3.16
PH1  (via drill 0.3)
  Top 0.178: IC3.13 31.17,5.75 30.4,4.98 23.29,4.98 v22.94,4.8
  Bottom 0.178: v22.94,4.8 22.94,5.33 21.69,6.58 18.96,6.58 U$3.14
PH2  (via drill 0.3)
  Top 0.178: IC3.14 31.56,5.42 v32.72,6.58 | v23.47,6.58 16.42,6.58 U$3.12
  Bottom 0.178: v32.72,6.58 32.72,5.87 31.11,4.27 30.05,4.27 29.52,4.98 25.07,4.98 v23.47,6.58
PH3  (via drill 0.3)
  Top 0.178: IC3.15 31.88,5.03 31.11,4.27 v29.16,4.27
  Bottom 0.178: v29.16,4.27 25.96,4.27 25.78,4.45 24.54,4.45 22.05,6.93 14.24,6.93 U$3.10
PH4
  Top 0.178: IC3.16 32.23,4.67 31.11,3.56 28.45,3.56 27.74,4.27 25.96,4.27 25.78,4.45 24,4.45 23.65,4.09 22.05,4.09 21.87,4.27 10.49,4.27 10.13,4.62 10.13,5.37 U$3.8
PH5  (via drill 0.3)
  Top 0.178: IC3.17 32.59,4.32 31.47,3.2 27.74,3.2 v27.38,3.56
  Bottom 0.178: v27.38,3.56 25.96,3.56 25.43,4.09 22.23,4.09 21.87,4.27 8,4.27 8,5.02 U$3.6
PH6
  Top 0.178: IC3.18 32.94,3.96 31.83,2.85 26.67,2.85 25.43,4.09 24.18,4.09 23.82,3.73 21.51,3.73 21.34,3.91 5.87,3.91 5.16,4.62 5.16,5.32 U$3.4
PH7  (via drill 0.3)
  Top 0.178: IC3.27 38.65,1.88 v39.83,0.71
  Bottom 0.178: v39.83,0.71 38.41,2.13 26.85,2.13 25.25,3.73 21.51,3.73 21.34,3.91 3.2,3.91 2.49,4.62 2.49,5.35 U$3.2
PJ0
  Top 0.178: IC3.63 44.42,19.02 44.98,19.74 46.6,21.17 U$1.2
PJ1
  Top 0.178: IC3.64 46.38,21.69 49.78,21.69 50.8,20.68 U$1.4
PJ2
  Top 0.178: IC3.65 46.03,22.05 51.92,22.05 53.33,20.64 U$1.6
PJ3
  Top 0.178: IC3.66 45.68,22.4 54.41,22.4 55.88,20.93 U$1.8
PJ4
  Top 0.178: IC3.67 45.33,22.76 57.07,22.76 58.42,21.41 U$1.10
PJ5  (via drill 0.3)
  Top 0.178: IC3.68 43.38,21.52 v43.38,22.58
  Bottom 0.178: v43.38,22.58 43.56,22.76 59.56,22.76 60.96,21.36 U$1.12
PJ6  (via drill 0.3)
  Top 0.178: IC3.69 41.96,20.8 v41.96,21.87 | v59.56,21.69 60.27,22.4 62.05,22.4 63.5,20.95 U$1.14
  Bottom 0.178: v41.96,21.87 45.16,21.87 45.7,22.4 58.85,22.4 v59.56,21.69
PJ7  (via drill 0.3)
  Top 0.178: IC3.79 37.16,17.46 37.16,17.07 37.52,16.71 v39.65,16.71
  Bottom 0.178: v39.65,16.71 42.49,19.56 65.08,19.56 66.04,20.52 U$1.16
PK0
  Top 0.178: U$5.16 20.99,20.64 21.87,21.51 25.43,21.51 27.2,19.74 27.82,19.74 IC3.89
PK1
  Top 0.178: U$5.14 18.66,20.64 19.74,21.87 25.6,21.87 27.38,20.27 28.09,20.09 30.23,17.96 30.3,17.96 IC3.88
PK2  (via drill 0.3)
  Top 0.178: v27.03,21.51 28.27,20.45 29.94,19.02 IC3.87
  Bottom 0.178: U$5.12 15.24,21.29 15.82,22.23 26.31,22.23 v27.03,21.51
PK3
  Top 0.178: U$5.10 12.7,21.41 13.16,22.23 27.38,22.23 27.91,21.34 28.63,20.98 30.29,19.38 IC3.86
PK4  (via drill 0.3)
  Top 0.178: v28.45,21.87 29.58,20.8 IC3.85
  Bottom 0.178: U$5.8 10.16,21.72 10.67,22.58 27.91,22.58 v28.45,21.87
PK5
  Top 0.178: U$5.6 7.62,21.67 8.18,22.58 28.98,22.58 29.16,21.87 29.57,21.51 IC3.84
PK6  (via drill 0.3)
  Top 0.178: v29.87,22.23 29.93,21.87 IC3.83
  Bottom 0.178: U$5.4 5.08,21.97 5.69,22.94 29.34,22.94 v29.87,22.23
PK7
  Top 0.178: U$5.2 2.54,21.74 3.38,22.94 30.1,22.94 30.58,22.58 30.63,22.05 IC3.82 33.24,19.21
PL0
  Top 0.178: IC3.35 41.43,4.62 43.56,2.49 47.89,2.49 U$2.1
PL1  (via drill 0.3)
  Top 0.178: IC3.36 41.78,4.98 43.92,2.85 46.41,2.85 v46.76,3.2
  Bottom 0.178: v46.76,3.2 46.76,2.49 47.65,1.6 49.54,1.6 U$2.3
PL2  (via drill 0.3)
  Top 0.178: IC3.37 42.23,5.42 v44.09,3.56 | v44.98,1.78 45.34,1.6 52.63,1.6 53.34,2.31 U$2.5
  Bottom 0.178: v44.09,3.56 44.98,2.67 v44.98,1.78
PL3
  Top 0.178: IC3.38 43.99,4.27 44.63,4.27 44.98,3.91 45.7,3.91 46.05,3.73 46.41,3.73 46.76,3.91 55.18,3.91 U$2.7
PL4  (via drill 0.3)
  Top 0.178: IC3.39 42.84,6.05 44.27,4.62 44.81,4.62 45.16,4.27 46.05,4.27 v46.23,4.45
  Bottom 0.178: v46.23,4.45 46.41,4.45 46.94,3.91 57.37,3.91 U$2.9
PL5
  Top 0.178: IC3.40 43.19,6.41 44.63,4.98 45.87,4.98 46.23,5.16 46.76,4.98 47.47,4.27 59.55,4.27 U$2.11
PL6  (via drill 0.3)
  Top 0.178: IC3.41 43.55,6.77 44.98,5.33 45.7,5.33 arc90 45.87,5.51 46.23,5.87 v46.41,5.87
  Bottom 0.178: v46.41,5.87 46.41,5.33 47.47,4.27 62.09,4.27 U$2.13
PL7  (via drill 0.3)
  Top 0.178: v45.52,6.04 45.04,6.04 IC3.42
  Bottom 0.178: U$2.15 66.04,1.14 65.79,0.89 46.94,0.89 45.7,2.13 45.52,3.02 v45.52,6.04
RESET  (via drill 0.3)
  Top 0.178: IC3.30 39.73,2.94 40.54,2.13 42.32,2.13 43.56,0.89 66.67,0.89 v67.21,1.42 | v69.88,1.42 75.03,1.42 75.56,1.96 75.56,21.87 v75.03,22.4
  Bottom 0.178: v67.21,1.42 v69.88,1.42 | U$1.20 72.54,20.64 C7.1 74.31,22.4 v75.03,22.4 74.85,22.23 R5.1
USB5V  (via drill 0.3)
  Top 0.178: R4.1 71.84,12.63 71.12,11.91 67.39,11.91 67.3,11.82 | C2.1 64.73,10.12 65.08,9.78 65.96,9.78 66.5,10.31 66.5,10.85 v65.25,12.09
  Top 0.305: v73.08,4.45 72.72,4.09 70.59,4.09 69.88,4.8 69.88,9.25 67.3,11.82 67.03,12.09 v65.25,12.09
  Bottom 0.178: 64.72,11.56 63.65,10.49 63.65,8.17 IC2.20
  Bottom 0.305: USB.1 66.5,13.34 v65.25,12.09 64.72,11.56 | v73.08,4.45 73.69,4.45 D1.2 75.29,1.77 SJ1.2
VCC  (via drill 0.3)
  Top 0.178: IC3.100 27.68,12.09 v32,12.09 | IC3.10 32.52,9.25 v32.54,9.25 | 39.08,4.23 37.69,5.69 38.05,7.11 36.8,7.82 36.09,8.28 v35.2,9.07 | 39.08,4.23 IC3.31 | 41.68,14.86 41.39,14.58 36.27,14.58 35.38,13.69 v35.38,13.34 | 41.68,14.86 IC3.61 | IC3.80 35.2,18.71 v35.2,16.18 | 41.68,14.86 44.27,12.27 v44.45,12.27 46.41,11.73 47.65,12.8 48.9,12.09 49.43,11.91 51.56,11.91 51.74,11.73 v54.05,11.73 | R3.2 73.08,6.39 73.08,5.33 73.25,5.16 73.61,5.16 73.97,4.8 73.97,2.67 v74.14,2.49 | v69.88,19.38 72.19,19.38 72.54,19.74 74.67,19.74 R5.2 v74.85,18.14 | v37.16,2.85 37.69,2.85 39.08,4.23
  Top 0.305: 68.58,0.84 U$2.17 | 68.58,0.84 68.1,0.41 43.03,0.41 v42.14,1.25 | v35.2,9.07 v34.67,6.58 | 68.58,0.84 68.71,0.71 v72.54,0.71
  Bottom 0.178: 33.6,10.31 v32.54,9.25 30.59,7.3 C4.2 | 33.6,10.31 33.96,10.67 34.42,11.13 IC1.4 34.42,12.38 v35.38,13.34 | 33.96,12.09 v32,12.09 | v35.2,9.07 33.96,10.31 33.6,10.31 | 35.56,15.29 35.56,15.82 v35.2,16.18 34.67,15.65 34.14,15.65 33.4,16.39 C5.2 | v54.05,11.73 57.07,11.73 57.96,9.96 59.92,9.96 60.27,10.67 60.27,15.35 IC2.4 60.31,16.57 60.63,16.89 67.39,16.89 67.56,17.07 67.56,17.08 U$1.17 68.59,18.1 v69.88,19.38 | v74.14,2.49 73.97,2.49 73.61,2.13 73.08,2.13 72.54,1.6 v72.54,0.71 | v74.85,18.14 R5.2 | C6.2 45.88,13.7 v44.45,12.27 | C8.2 36.6,3.4 v37.16,2.85
  Bottom 0.305: C8*.1 37.51,15.29 35.56,15.29 33.96,13.69 33.96,12.09 33.96,10.67 | v42.14,1.25 41.71,1.6 39.79,3.52 38.41,3.88 37.12,4.98 35.56,6.76 v34.67,6.58 | v72.54,0.71 72.9,1.07 SJ1.1
VIN
  Bottom 0.305: C7*.1 | C7*.1 IC1.3 40.72,8 39.08,8 38.73,7.64 33.96,7.64 33.43,6.93 33.43,5.69 34.14,5.16 35.38,6.04 36.27,4.98 38.05,3.38 39.29,3.02 41.78,0.41 70.76,0.41 71.12,0.71 U$2.19 72.98,2.86 D1.1

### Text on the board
JKD_ARDUINO: 15 | 14 | 13 | 12 | 11 | 10 | 9 | 8 | 15 | RXD3 | 14 | TXD3 | J2 | J3 | J4 | J5 | J6 | J7 | 39 | RESET | Analog | 7 | 6 | 5 | 4 | 3 | 2 | 1 | 0 | 30 | 31 | 32 | 33 | 34 | 35 | 36 | 37 | 5V | GND | (C)2011 JK Devices | 4 | 22 | 23 | 24 | 25 | 26 | 27 | 28 | 29 | 3.3V | CC-BY-SA 3.0 | 40 | GND | AREF | E7 | 41 | E6 | 3 | PWM | 2 | PWM | 5 | PWM | E2 | 1 | TX0 | 0 | RX0 | GND | 9 | PWM | 8 | PWM | 7 | PWM | 6 | PWM | H2 | 16 | TXD2 | 17 | RXD2 | GND | 21 | 20 | 19 | TXD1 | 18 | D4 | D5 | D6 | 38 | GND | H7 | SCL | SDA | RXD1 | POWER | MEGAMINI R3 | 13 | 12 | 11 | 10 | 50 | 51 | 52 | 53 | http://jkd.gs/100 | 49 | 48 | 47 | 46 | 45 | 44 | 43 | 42 | 5V | VIN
